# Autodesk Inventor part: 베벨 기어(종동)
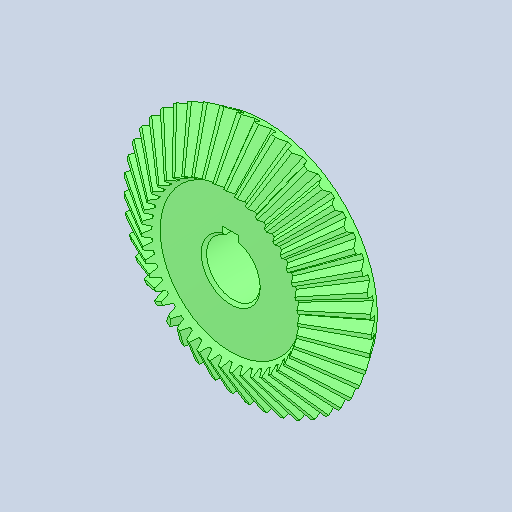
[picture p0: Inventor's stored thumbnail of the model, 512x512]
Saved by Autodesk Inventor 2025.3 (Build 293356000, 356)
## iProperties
Created: 2026-01
Part Number: 베벨 기어(종동)
Material: 강철, 합금
Document SubType Name: Modeling
Designer: PC-13
Density: 7.73 g/cm^3
Appearance: 기본값
Author: jhkim
Sending System: Autodesk Inventor 2026
Preprocessor: ST-DEVELOPER v20.1
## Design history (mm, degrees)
feature "Solid1"
node "솔리드1"
